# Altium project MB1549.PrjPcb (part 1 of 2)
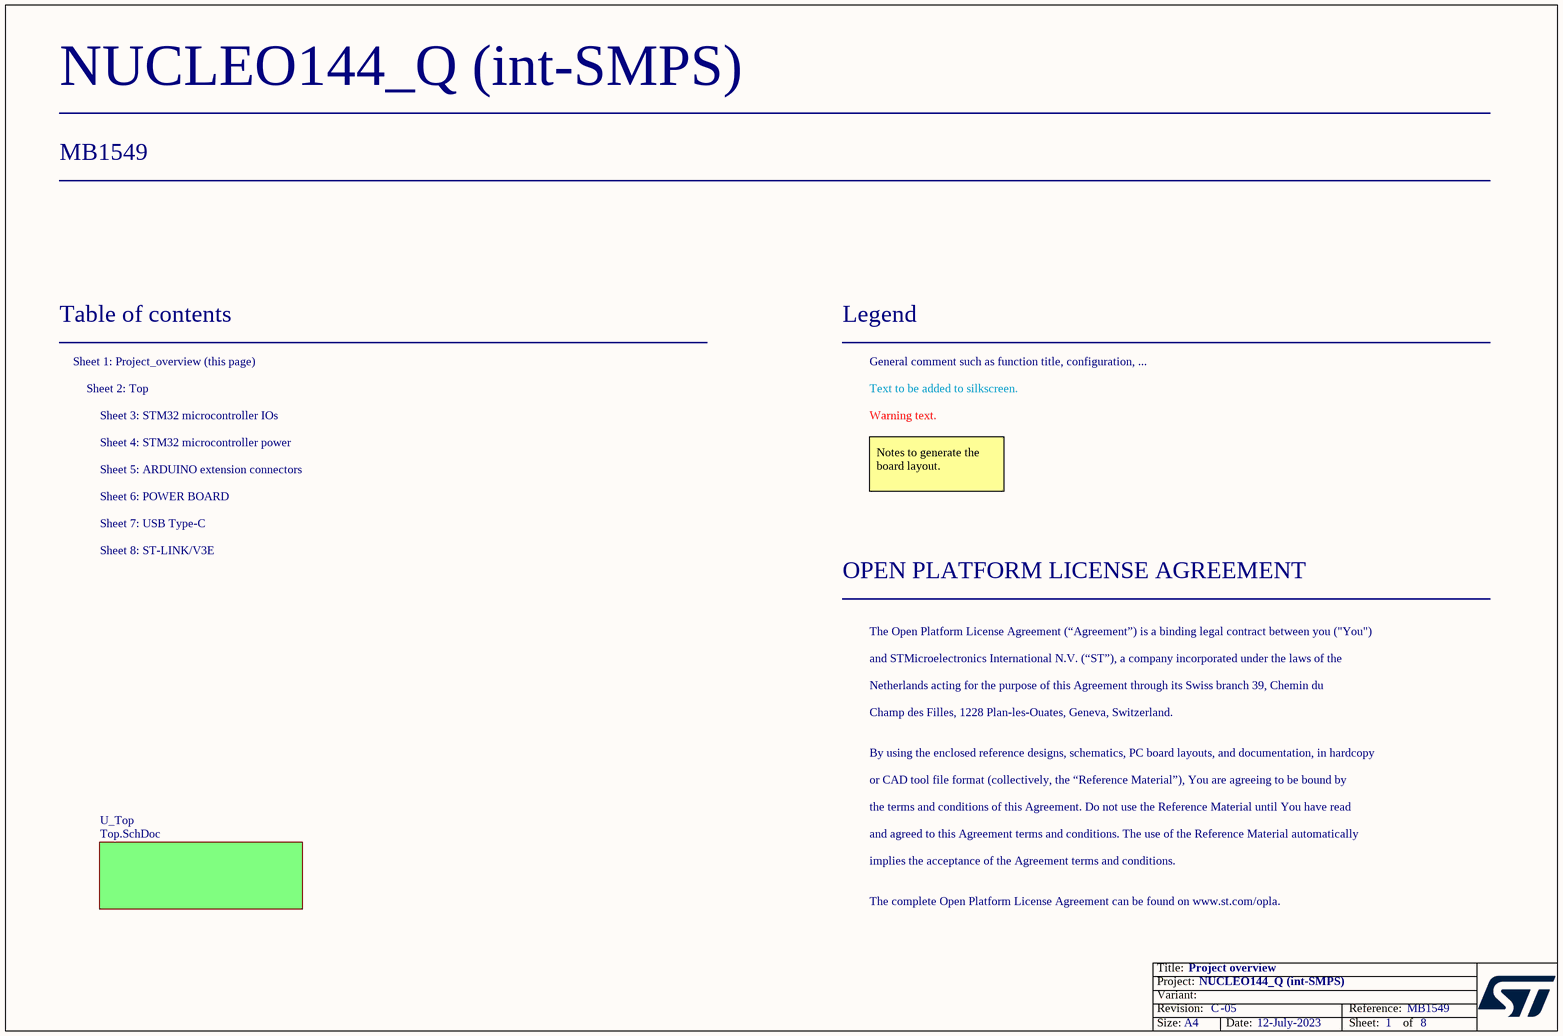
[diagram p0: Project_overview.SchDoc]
Board_Reference: MB1549; Board_PCB_Revision: C; Board_Name: NUCLEO144_Q (int-SMPS); Board_Document_Date: 12-July-2023; Board_Assembly_Revision: 05
8 sheets, 291 parts. Net scope: flat (ports and power ports of the same name join across sheets).
Board file: MB1549.PcbDoc
Sheets:
  Project_overview.SchDoc
    U_Top = Top.SchDoc
      U_STM32_microcontroller_IOs = STM32_microcontroller_IOs.SchDoc
      U_STM32_microcontroller_power = STM32_microcontroller_power.SchDoc
      U_ARDUINO_extension_connectors = ARDUINO_extension_connectors.SchDoc
      U_USB_Type_C = USB_Type_C.SchDoc
      U_POWER_BOARD = POWER_BOARD.SchDoc
      U_ST_LINK_V3E = ST_LINK_V3E.SchDoc

## Sheet Project_overview.SchDoc: Project overview
size A4; Date: Not used; ApprovedBy: Not used; CheckedBy: Not used; Author: Not used; CompanyName: STMicroelectronics; DrawnBy: Not used; Engineer: Not used; Organization: Not used; Address1: Not used; Address2: Not used; Address3: Not used; Address4: Not used; DocumentNumber: 1; Revision: Not used; SheetNumber: 1; SheetTotal: 8

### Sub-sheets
U_Top = Top.SchDoc: no entries

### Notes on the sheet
- Table of contents
- Sheet 1: Project_overview (this page)
- Legend
- General comment such as function title, configuration, ...
- Sheet 2: Top
- Sheet 4: STM32 microcontroller power
- Sheet 3: STM32 microcontroller IOs
- Text to be added to silkscreen.
- Warning text.
- Sheet 6: POWER BOARD
- Sheet 5: ARDUINO extension connectors
- Notes to generate the board layout.
- Sheet 8: ST-LINK/V3E
- Sheet 7: USB Type-C
- OPEN PLATFORM LICENSE AGREEMENT
- The Open Platform License Agreement (“Agreement”) is a binding legal contract between you ("You")
- and STMicroelectronics International N.V. (“ST”), a company incorporated under the laws of the
- Netherlands acting for the purpose of this Agreement through its Swiss branch 39, Chemin du
- Champ des Filles, 1228 Plan-les-Ouates, Geneva, Switzerland.
- By using the enclosed reference designs, schematics, PC board layouts, and documentation, in hardcopy
- or CAD tool file format (collectively, the “Reference Material”), You are agreeing to be bound by
- the terms and conditions of this Agreement. Do not use the Reference Material until You have read
- and agreed to this Agreement terms and conditions. The use of the Reference Material automatically
- implies the acceptance of the Agreement terms and conditions.
- The complete Open Platform License Agreement can be found on www.st.com/opla.

## Sheet Top.SchDoc: Top: hierarchical view
size A4; Date: Not used; ApprovedBy: Not used; CheckedBy: Not used; Author: Not used; CompanyName: STMicroelectronics; DrawnBy: Not used; Engineer: Not used; Organization: Not used; Address1: Not used; Address2: Not used; Address3: Not used; Address4: Not used; DocumentNumber: 2; Revision: A-01-P3; SheetNumber: 2; SheetTotal: 8
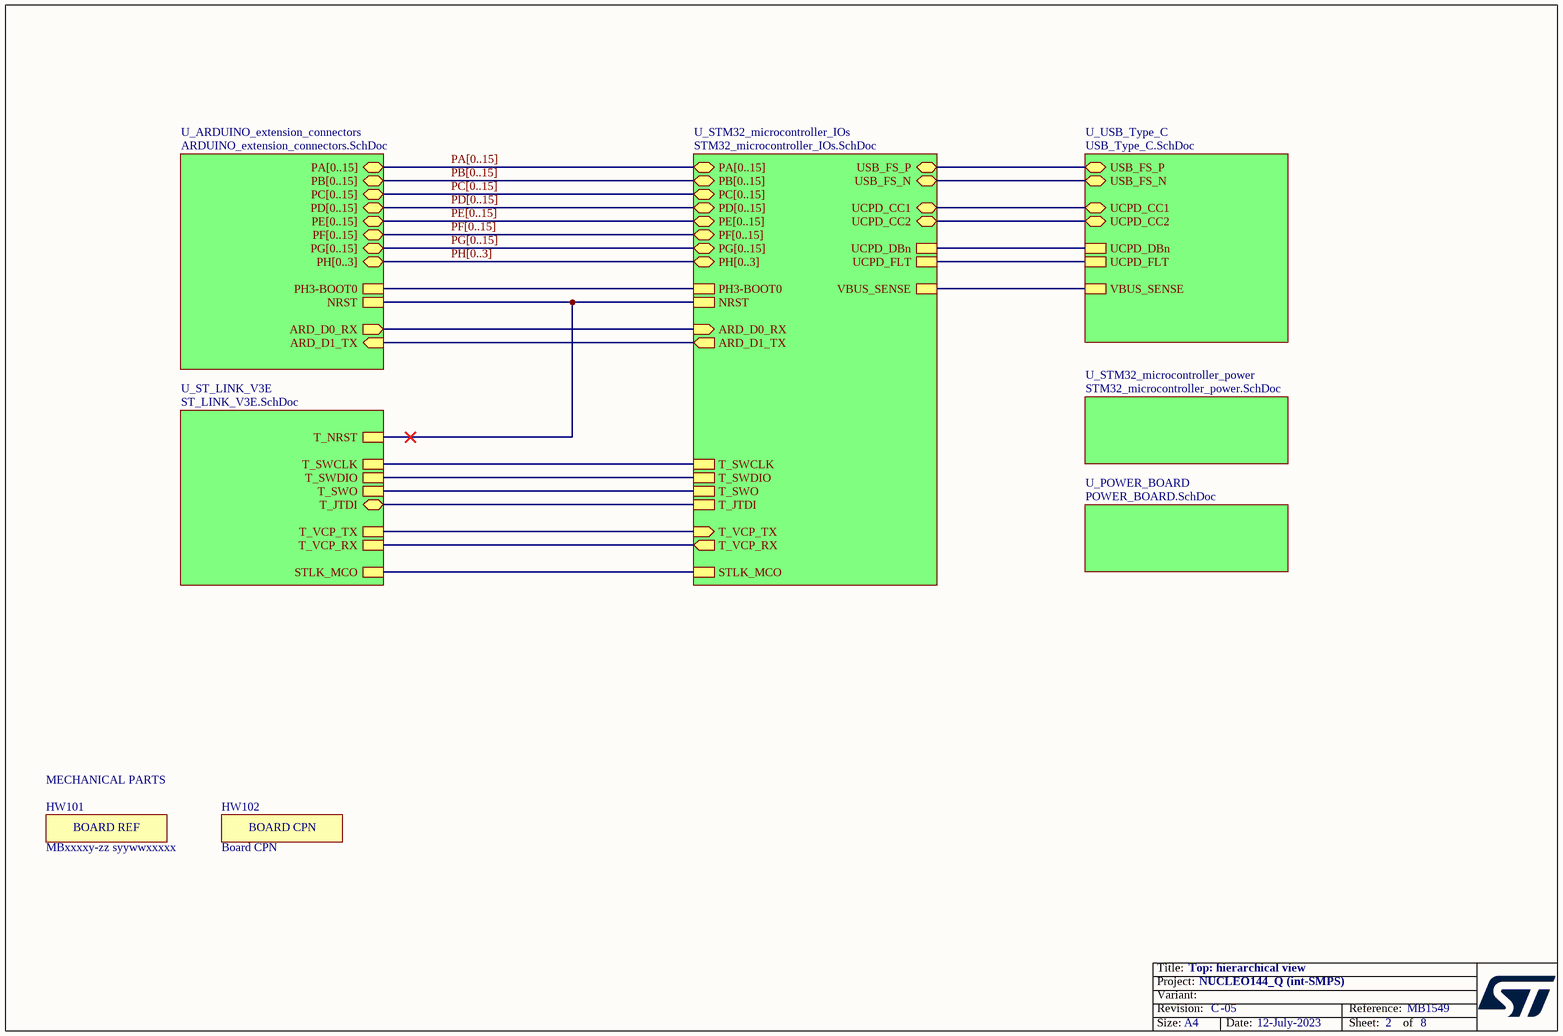
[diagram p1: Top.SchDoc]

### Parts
HW101  value MBxxxxy-zz syywwxxxxx  [STICKER_25X9]  (hidden comment: STICKER_BOARD_REF)  (no BOM)
HW102  value Board CPN  [STICKER_25X9]  (hidden comment: STICKER_BOARD_CPN)  (no BOM)

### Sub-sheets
U_ARDUINO_extension_connectors = ARDUINO_extension_connectors.SchDoc: PA[0..15] (bidir), PB[0..15] (bidir), PC[0..15] (bidir), NRST, PH3-BOOT0, PD[0..15] (bidir), PE[0..15] (bidir), PF[0..15] (bidir), PG[0..15] (bidir), PH[0..3] (bidir), ARD_D0_RX (out), ARD_D1_TX (in)
U_POWER_BOARD = POWER_BOARD.SchDoc: no entries
U_ST_LINK_V3E = ST_LINK_V3E.SchDoc: T_SWDIO, STLK_MCO, T_JTDI (bidir), T_SWO, T_VCP_TX, T_SWCLK, T_VCP_RX, T_NRST
U_STM32_microcontroller_IOs = STM32_microcontroller_IOs.SchDoc: NRST, PA[0..15] (bidir), PB[0..15] (bidir), PC[0..15] (bidir), PD[0..15] (bidir), PE[0..15] (bidir), PF[0..15] (bidir), PG[0..15] (bidir), PH[0..3] (bidir), PH3-BOOT0, ARD_D0_RX (in), ARD_D1_TX (out), UCPD_DBn, UCPD_FLT, VBUS_SENSE, UCPD_CC2 (bidir), USB_FS_P (bidir), UCPD_CC1 (bidir), USB_FS_N (bidir), T_VCP_TX (in), T_VCP_RX (out), T_SWCLK, T_SWDIO, STLK_MCO, T_SWO, T_JTDI
U_STM32_microcontroller_power = STM32_microcontroller_power.SchDoc: no entries
U_USB_Type_C = USB_Type_C.SchDoc: UCPD_CC1 (bidir), UCPD_CC2 (bidir), UCPD_DBn, UCPD_FLT, USB_FS_P (bidir), VBUS_SENSE, USB_FS_N (bidir)

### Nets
(unnamed): sheet U_STM32_microcontroller_IOs/NRST, sheet U_ARDUINO_extension_connectors/NRST, sheet U_ST_LINK_V3E/T_NRST
(unnamed): sheet U_STM32_microcontroller_IOs/PH3-BOOT0, sheet U_ARDUINO_extension_connectors/PH3-BOOT0  [a separate net that carries the same name]
(unnamed): sheet U_STM32_microcontroller_IOs/ARD_D0_RX, sheet U_ARDUINO_extension_connectors/ARD_D0_RX  [a separate net that carries the same name]
(unnamed): sheet U_STM32_microcontroller_IOs/ARD_D1_TX, sheet U_ARDUINO_extension_connectors/ARD_D1_TX  [a separate net that carries the same name]
(unnamed): sheet U_STM32_microcontroller_IOs/UCPD_DBn, sheet U_USB_Type_C/UCPD_DBn  [a separate net that carries the same name]
(unnamed): sheet U_STM32_microcontroller_IOs/UCPD_FLT, sheet U_USB_Type_C/UCPD_FLT  [a separate net that carries the same name]
(unnamed): sheet U_STM32_microcontroller_IOs/VBUS_SENSE, sheet U_USB_Type_C/VBUS_SENSE  [a separate net that carries the same name]
(unnamed): sheet U_STM32_microcontroller_IOs/UCPD_CC2, sheet U_USB_Type_C/UCPD_CC2  [a separate net that carries the same name]
(unnamed): sheet U_STM32_microcontroller_IOs/USB_FS_P, sheet U_USB_Type_C/USB_FS_P  [a separate net that carries the same name]
(unnamed): sheet U_STM32_microcontroller_IOs/UCPD_CC1, sheet U_USB_Type_C/UCPD_CC1  [a separate net that carries the same name]
(unnamed): sheet U_STM32_microcontroller_IOs/USB_FS_N, sheet U_USB_Type_C/USB_FS_N  [a separate net that carries the same name]
(unnamed): sheet U_STM32_microcontroller_IOs/T_VCP_TX, sheet U_ST_LINK_V3E/T_VCP_TX  [a separate net that carries the same name]
(unnamed): sheet U_STM32_microcontroller_IOs/T_VCP_RX, sheet U_ST_LINK_V3E/T_VCP_RX  [a separate net that carries the same name]
(unnamed): sheet U_STM32_microcontroller_IOs/T_SWCLK, sheet U_ST_LINK_V3E/T_SWCLK  [a separate net that carries the same name]
(unnamed): sheet U_STM32_microcontroller_IOs/T_SWDIO, sheet U_ST_LINK_V3E/T_SWDIO  [a separate net that carries the same name]
(unnamed): sheet U_STM32_microcontroller_IOs/STLK_MCO, sheet U_ST_LINK_V3E/STLK_MCO  [a separate net that carries the same name]
(unnamed): sheet U_STM32_microcontroller_IOs/T_SWO, sheet U_ST_LINK_V3E/T_SWO  [a separate net that carries the same name]
(unnamed): sheet U_STM32_microcontroller_IOs/T_JTDI, sheet U_ST_LINK_V3E/T_JTDI  [a separate net that carries the same name]

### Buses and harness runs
bus PA[0..15] = sheet U_ARDUINO_extension_connectors/PA[0..15] = sheet U_STM32_microcontroller_IOs/PA[0..15]
bus PB[0..15] = sheet U_ARDUINO_extension_connectors/PB[0..15] = sheet U_STM32_microcontroller_IOs/PB[0..15]
bus PC[0..15] = sheet U_ARDUINO_extension_connectors/PC[0..15] = sheet U_STM32_microcontroller_IOs/PC[0..15]
bus PD[0..15] = sheet U_ARDUINO_extension_connectors/PD[0..15] = sheet U_STM32_microcontroller_IOs/PD[0..15]
bus PE[0..15] = sheet U_ARDUINO_extension_connectors/PE[0..15] = sheet U_STM32_microcontroller_IOs/PE[0..15]
bus PF[0..15] = sheet U_ARDUINO_extension_connectors/PF[0..15] = sheet U_STM32_microcontroller_IOs/PF[0..15]
bus PG[0..15] = sheet U_ARDUINO_extension_connectors/PG[0..15] = sheet U_STM32_microcontroller_IOs/PG[0..15]
bus PH[0..3] = sheet U_ARDUINO_extension_connectors/PH[0..3] = sheet U_STM32_microcontroller_IOs/PH[0..3]

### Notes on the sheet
- (near HW101) MECHANICAL PARTS

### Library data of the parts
HW101 = MCD-00235: Sticker to mention board reference + serial number; Part_Type: Mechanical; Provided_By: SUBCO
HW102 = MCD-00547: Sticker to mention board CPN code; Part_Type: Mechanical; Provided_By: SUBCO

## Sheet STM32_microcontroller_IOs.SchDoc: STM32_microcontroller_IOs
size A4; Date: Not used; ApprovedBy: Not used; CheckedBy: Not used; Author: Not used; CompanyName: STMicroelectronics; DrawnBy: Not used; Engineer: Not used; Organization: Not used; Address1: Not used; Address2: Not used; Address3: Not used; Address4: Not used; DocumentNumber: 3; Revision: Not used; SheetNumber: 3; SheetTotal: 8
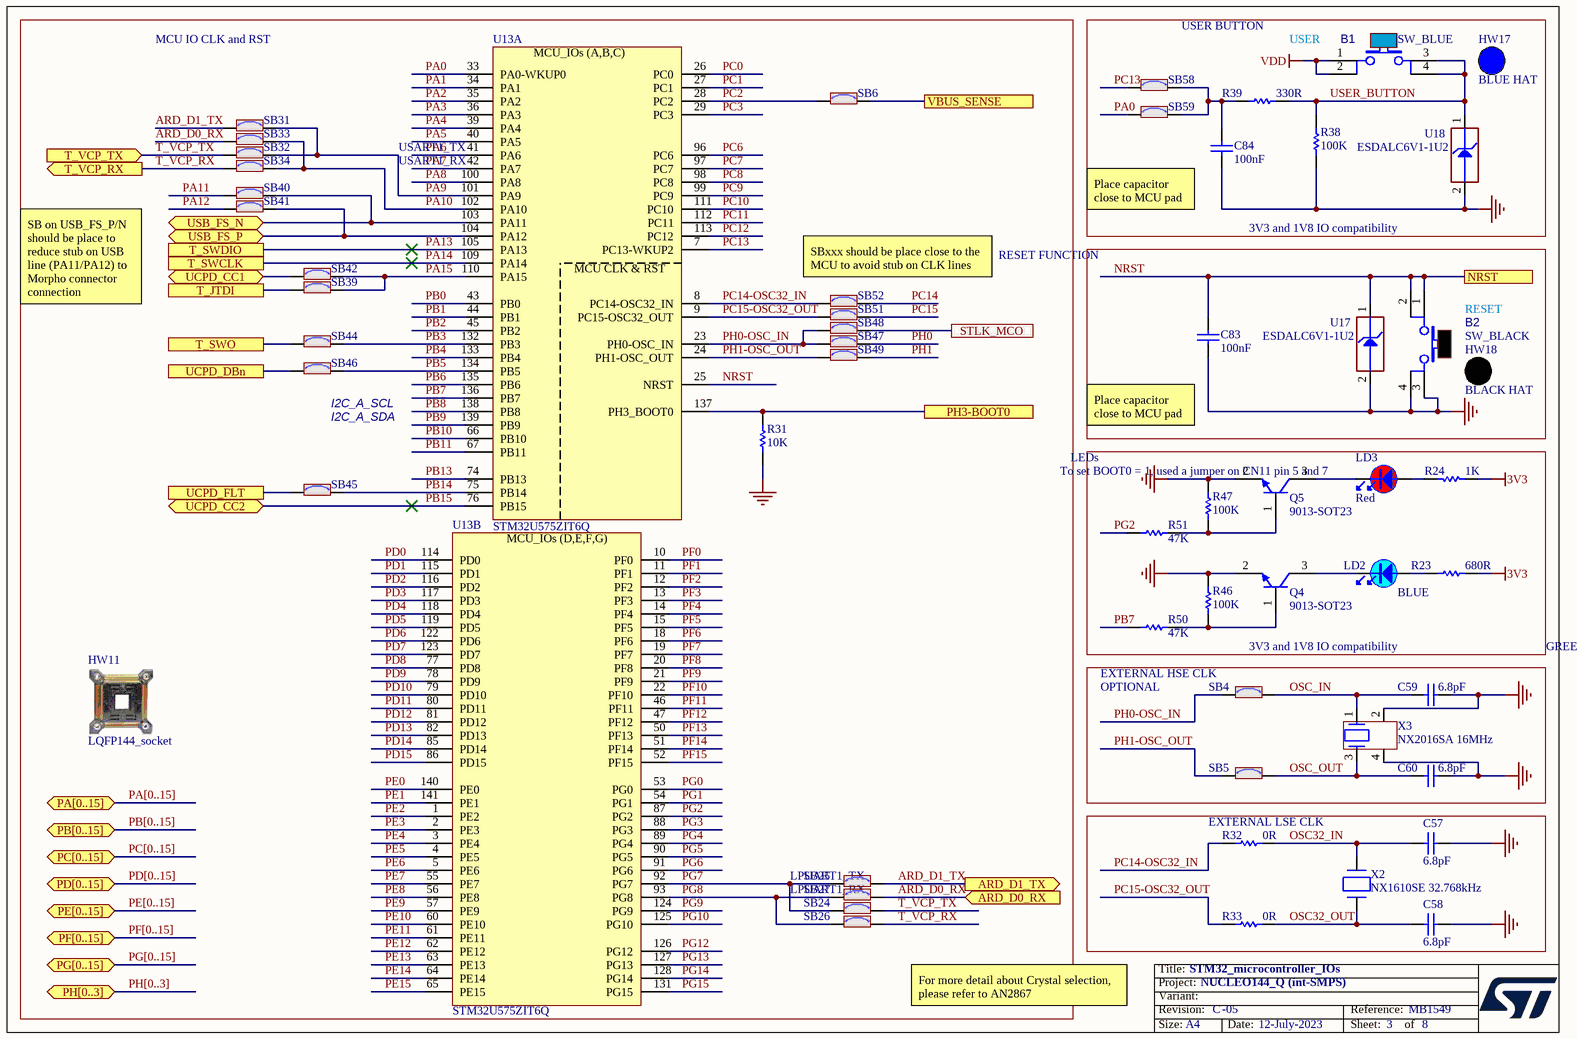
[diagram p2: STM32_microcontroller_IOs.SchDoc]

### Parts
B1  value SW_BLUE  [SWI_WEALTHMETAL_TD-0341_4P_BLUE]
B2  value SW_BLACK  [SWI_WEALTHMETAL_TD-0341_4P_BLACK]
C57  value 6.8pF  [C0402]  (hidden comment: Capacitor)
C58  value 6.8pF  [C0402]  (hidden comment: Capacitor)
C59  value 6.8pF  [C0402]  (hidden comment: Capacitor)
C60  value 6.8pF  [C0402]  (hidden comment: Capacitor)
C83  value 100nF  [C0402]
C84  value 100nF  [C0402]
HW11  value LQFP144_socket  (mechanical)
HW17  value BLUE HAT  (mechanical)
HW18  value BLACK HAT  (mechanical)
LD2  value BLUE  [LED_0603_VISHAY_VLMB1300-GS08_BLUE_1A2K_H0P8]
LD3  value Red  [LED_0603_RED]  (hidden comment: LED_red)
Q4  value 9013-SOT23  [NPN_SOT23]
Q5  value 9013-SOT23  [NPN_SOT23]
R23  value 680R  [R0603]
R24  value 1K  [R0603]
R31  value 10K  [R0402]  (hidden comment: Resistor)
R32  value 0R  [R0603]
R33  value 0R  [R0603]
R38  value 100K  [R0603]
R39  value 330R  [R0603]
R46  value 100K  [R0603]
R47  value 100K  [R0603]
R50  value 47K  [R0603]
R51  value 47K  [R0603]
SB4  (no value)  [SOLDER-BRIDGE_R0603-0R]
SB5  (no value)  [SOLDER-BRIDGE_R0603-0R]
SB6  (no value)  [SOLDER-BRIDGE_R0603-0R]
SB24  (no value)  [SOLDER-BRIDGE_R0603-0R]
SB25  (no value)  [SOLDER-BRIDGE_R0603-0R]
SB26  (no value)  [SOLDER-BRIDGE_R0603-0R]
SB27  (no value)  [SOLDER-BRIDGE_R0603-0R]
SB31  (no value)  [SOLDER-BRIDGE_R0603-0R]
SB32  (no value)  [SOLDER-BRIDGE_R0603-0R]
SB33  (no value)  [SOLDER-BRIDGE_R0603-0R]
SB34  (no value)  [SOLDER-BRIDGE_R0603-0R]
SB39  (no value)  [SOLDER-BRIDGE_R0603-0R]
SB40  (no value)  [SOLDER-BRIDGE_R0603-0R]
SB41  (no value)  [SOLDER-BRIDGE_R0603-0R]
SB42  (no value)  [SOLDER-BRIDGE_R0603-0R]
SB44  (no value)  [SOLDER-BRIDGE_R0603-0R]
SB45  (no value)  [SOLDER-BRIDGE_R0603-0R]
SB46  (no value)  [SOLDER-BRIDGE_R0603-0R]
SB47  (no value)  [SOLDER-BRIDGE_R0603-0R]
SB48  (no value)  [SOLDER-BRIDGE_R0603-0R]
SB49  (no value)  [SOLDER-BRIDGE_R0603-0R]
SB51  (no value)  [SOLDER-BRIDGE_R0603-0R]
SB52  (no value)  [SOLDER-BRIDGE_R0603-0R]
SB58  (no value)  [SOLDER-BRIDGE_R0603-0R]
SB59  (no value)  [SOLDER-BRIDGE_R0603-0R]
U13  value STM32U575ZIT6Q  [ICC_LQFP144_20X20_P050]  (hidden comment: STM32U575ZIT6QU)  (parts A,B of 3)
U17  value ESDALC6V1-1U2  [ESD_ST0201]
U18  value ESDALC6V1-1U2  [ESD_ST0201]
X2  value NX1610SE 32.768kHz  [CRY_NX1610SE_2P]  (hidden comment: XTAL_2_PINS)
X3  value NX2016SA 16MHz  [CRY_NX2016SA_4P]  (hidden comment: XTAL_4_PINS)

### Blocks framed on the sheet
EXTERNAL LSE CLK: C57 C58 R32 R33 X2

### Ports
ARD_D0_RX (in), ARD_D1_TX (out), NRST, PA[0..15] (bidir), PB[0..15] (bidir), PC[0..15] (bidir), PD[0..15] (bidir), PE[0..15] (bidir), PF[0..15] (bidir), PG[0..15] (bidir), PH3-BOOT0, PH[0..3] (bidir), STLK_MCO, T_JTDI, T_SWCLK, T_SWDIO, T_SWO, T_VCP_RX (out), T_VCP_TX (in), UCPD_CC1 (bidir), UCPD_CC2 (bidir), UCPD_DBn, UCPD_FLT, USB_FS_N (bidir), USB_FS_P (bidir), VBUS_SENSE

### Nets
3V3: R23.1 R24.1
GND: B2.3 B2.4 C57.2 C58.2 C59.2 C60.2 C83.1 C84.1 Q4.2(E) Q5.2(E) R31.2 R38.1 R46.1 R47.1 U17.2(GND) U18.2(GND) X3.2 X3.4
VDD: B1.1 B1.2
ARD_D0_RX: SB27.1 SB33.2 ; port ARD_D0_RX
ARD_D1_TX: SB25.1 SB31.2 ; port ARD_D1_TX
NRST: B2.1 B2.2 C83.2 U13.25(NRST) U17.1(IO1) ; port NRST
OSC32_IN: C57.1 R32.2 X2.2(X2)
OSC32_OUT: C58.1 R33.2 X2.1(X1)
OSC_IN: C59.1 SB4.2 X3.1
OSC_OUT: C60.1 SB5.2 X3.3
PA0: SB59.2 U13.33(PA0-WKUP0)
PA1: U13.34(PA1)
PA2: U13.35(PA2)
PA3: U13.36(PA3)
PA4: U13.39(PA4)
PA5: U13.40(PA5)
PA6: U13.41(PA6)
PA7: U13.42(PA7)
PA8: U13.100(PA8)
PA9: SB31.1 SB32.1 U13.101(PA9)
PA10: SB33.1 SB34.1 U13.102(PA10)
PA11: SB40.1
PA12: SB41.1
PA13: U13.105(PA13) ; port T_SWDIO
PA14: U13.109(PA14) ; port T_SWCLK
PA15: SB39.2 SB42.2 U13.110(PA15)
PB0: U13.43(PB0)
PB1: U13.44(PB1)
PB2: U13.45(PB2)
PB3: SB44.2 U13.132(PB3)
PB4: U13.133(PB4)
PB5: SB46.2 U13.134(PB5)
PB6: U13.135(PB6)
PB7: R50.1 U13.136(PB7)
PB8: U13.138(PB8)
PB9: U13.139(PB9)
PB10: U13.66(PB10)
PB11: U13.67(PB11)
PB13: U13.74(PB13)
PB14: SB45.2 U13.75(PB14)
PB15: U13.76(PB15) ; port UCPD_CC2
PC0: U13.26(PC0)
PC1: U13.27(PC1)
PC2: SB6.1 U13.28(PC2)
PC3: U13.29(PC3)
PC6: U13.96(PC6)
PC7: U13.97(PC7)
PC8: U13.98(PC8)
PC9: U13.99(PC9)
PC10: U13.111(PC10)
PC11: U13.112(PC11)
PC12: U13.113(PC12)
PC13: SB58.2 U13.7(PC13-WKUP2)
PC14: SB52.2
PC14-OSC32_IN: R32.1 SB52.1 U13.8(PC14-OSC32_IN)
PC15: SB51.2
PC15-OSC32_OUT: R33.1 SB51.1 U13.9(PC15-OSC32_OUT)
PD0: U13.114(PD0)
PD1: U13.115(PD1)
PD2: U13.116(PD2)
PD3: U13.117(PD3)
PD4: U13.118(PD4)
PD5: U13.119(PD5)
PD6: U13.122(PD6)
PD7: U13.123(PD7)
PD8: U13.77(PD8)
PD9: U13.78(PD9)
PD10: U13.79(PD10)
PD11: U13.80(PD11)
PD12: U13.81(PD12)
PD13: U13.82(PD13)
PD14: U13.85(PD14)
PD15: U13.86(PD15)
PE0: U13.140(PE0)
PE1: U13.141(PE1)
PE2: U13.1(PE2)
PE3: U13.2(PE3)
PE4: U13.3(PE4)
PE5: U13.4(PE5)
PE6: U13.5(PE6)
PE7: U13.55(PE7)
PE8: U13.56(PE8)
PE9: U13.57(PE9)
PE10: U13.60(PE10)
PE11: U13.61(PE11)
PE12: U13.62(PE12)
PE13: U13.63(PE13)
PE14: U13.64(PE14)
PE15: U13.65(PE15)
PF0: U13.10(PF0)
PF1: U13.11(PF1)
PF2: U13.12(PF2)
PF3: U13.13(PF3)
PF4: U13.14(PF4)
PF5: U13.15(PF5)
PF6: U13.18(PF6)
PF7: U13.19(PF7)
PF8: U13.20(PF8)
PF9: U13.21(PF9)
PF10: U13.22(PF10)
PF11: U13.46(PF11)
PF12: U13.47(PF12)
PF13: U13.50(PF13)
PF14: U13.51(PF14)
PF15: U13.52(PF15)
PG0: U13.53(PG0)
PG1: U13.54(PG1)
PG2: R51.1 U13.87(PG2)
PG3: U13.88(PG3)
PG4: U13.89(PG4)
PG5: U13.90(PG5)
PG6: U13.91(PG6)
PG7: SB24.2 SB25.2 U13.92(PG7)
PG8: SB26.2 SB27.2 U13.93(PG8)
PG9: U13.124(PG9)
PG10: U13.125(PG10)
PG12: U13.126(PG12)
PG13: U13.127(PG13)
PG14: U13.128(PG14)
PG15: U13.131(PG15)
PH0: SB47.2
PH0-OSC_IN: SB4.1 SB47.1 SB48.1 U13.23(PH0-OSC_IN)
PH1: SB49.2
PH1-OSC_OUT: SB5.1 SB49.1 U13.24(PH1-OSC_OUT)
PH3-BOOT0: R31.1 U13.137(PH3_BOOT0) ; port PH3-BOOT0
STLK_MCO: SB48.2 ; port STLK_MCO
T_JTDI: SB39.1 ; port T_JTDI
T_SWO: SB44.1 ; port T_SWO
T_VCP_RX: SB26.1 SB34.2 ; port T_VCP_RX
T_VCP_TX: SB24.1 SB32.2 ; port T_VCP_TX
UCPD_CC1: SB42.1 ; port UCPD_CC1
UCPD_DBn: SB46.1 ; port UCPD_DBn
UCPD_FLT: SB45.1 ; port UCPD_FLT
USB_FS_N: SB40.2 U13.103(PA11) ; port USB_FS_N
USB_FS_P: SB41.2 U13.104(PA12) ; port USB_FS_P
USER_BUTTON: B1.3 B1.4 R38.2 R39.2 U18.1(IO1)
VBUS_SENSE: SB6.2 ; port VBUS_SENSE
NetC84_2: C84.2 R39.1 SB58.1 SB59.1
NetLD2_1: LD2.1 R23.2
NetLD2_2: LD2.2 Q4.3(C)
NetLD3_1: LD3.1 R24.2
NetLD3_2: LD3.2 Q5.3(C)
NetQ4_1: Q4.1(B) R46.2 R50.2
NetQ5_1: Q5.1(B) R47.2 R51.2

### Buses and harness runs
bus PA[0..15] = port PA[0..15]
bus PB[0..15] = port PB[0..15]
bus PC[0..15] = port PC[0..15]
bus PD[0..15] = port PD[0..15]
bus PE[0..15] = port PE[0..15]
bus PF[0..15] = port PF[0..15]
bus PG[0..15] = port PG[0..15]
bus PH[0..3] = port PH[0..3]

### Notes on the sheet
- MCU IO CLK and RST
- USER BUTTON
- USER
- USART1_TX
- USART1_RX
- (near C84) Place capacitor close to MCU pad
- 3V3 and 1V8 IO compatibility
- SB on USB_FS_P/N should be place to reduce stub on USB line (PA11/PA12) to Morpho connector connection
- SBxxx should be place close to the MCU to avoid stub on CLK lines
- RESET FUNCTION
- RESET
- (near SB46) I2C_A_SCL
- (near SB46) I2C_A_SDA
- (near C83) Place capacitor close to MCU pad
- (near R31) To set BOOT0 = 1, used a jumper on CN11 pin 5 and 7
- LEDs
- (near R50) 3V3 and 1V8 IO compatibility
- (near C59) GREEN LED IS ON ARDUINO SHEET
- EXTERNAL HSE CLK
- OPTIONAL
- LPUART1_TX
- LPUART1_RX
- For more detail about Crystal selection, please refer to AN2867

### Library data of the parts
B1 = MCD-00002: Non-Open Push-Button 0.1A 24V BLUE; Manufacturer_Part_Number: TD0341X-G01-BLU; Manufacturer: WEALTHMETAL; Part_Type: Misc; Provided_By: Subcon; Initial_Board_Reference: MB1274
B2 = MCD-00001: Non-Open Push-Button 0.1A 24V BLACK; Manufacturer_Part_Number: TD0341X-G01-BLA; Manufacturer: WEALTHMETAL; Part_Type: Misc; Provided_By: Subcon; Initial_Board_Reference: MB1274
C57 C58 = MCD-00674: Capacitor, MLCC, 6.8pF, 50V, NPO, +/-0.25pF, 0402, T=0.5mm; Part_Preference: Recommended; Manufacturer: YAGEO; Manufacturer_Part_Number: CC0402CRNPO9BN6R8; Component_Country_Of_Origin: China; ShowFields: YES; ID: 3068
C59 C60 = MCD-00674: Capacitor, MLCC, 6.8pF, 50V, NPO, +-0.25pF, 0402, T=0.5mm; Manufacturer_Part_Number: CC0402CRNPO9BN6R8; Manufacturer: YAGEO; Provided_By: Subcon; Initial_Board_Reference: MB1319
C83 C84 = MCD-00006: Capacitor, MLCC, 100nF, 16V, X7R, 10%, 0402, T=0.5mm; Manufacturer_Part_Number: CC0402KRX7R7BB104; Manufacturer: YAGEO; Alternate_Manufacturer_Part_Number: GCM155R71C104KA55D; Alternate_Manufacturer: MURATA; Provided_By: SUBCO; ECCN_US: EAR99; ECCN_EU: NEC
HW11 = MCD-01015: Yamaichi socket for LQFP144, with positioning pins.; Part_Type: Misc; Manufacturer_Part_Number: IC149-144-145-B5; Provided_By: Subcon; Initial_Board_Reference: MB1361; Remark: No footprint, mechanical part for BOM
HW17 = MCD-00634: Blue Hat for switch TD0341X-G01-BLU; Part_Type: Mechanical; Manufacturer_Part_Number: 988.16.09.3.00002_SH-517; Manufacturer: JIUBABA; Provided_By: Subcon; Initial_Board_Reference: MB1319
HW18 = MCD-00635: Black Hat for switch TD0341X-G01-BLA; Part_Type: Mechanical; Manufacturer_Part_Number: 988.16.09.3.00003_SH-517; Manufacturer: JIUBABA; Provided_By: Subcon; Initial_Board_Reference: MB1319
LD2 = MCD-00584: LED Blue, 0603 SMD, 3.3 V Forward Voltage; Part_Type: Display; Manufacturer_Part_Number: VLMB1300-GS08; Manufacturer: VISHAY; Order_Code_RS: 7730430; Provided_By: Subcon; Initial_Board_Reference: MB1331
LD3 = MCD-02899: LED, Red, 2V35, 20mA, 0603; Part_Type: Display; Part_Preference: Recommended; Manufacturer: EVERLIGHT; Manufacturer_Part_Number: 19-213/R6C-AP1Q2B/5T; Full_Alternate_Internal_Part_Number: MCD-00049; Component_Country_Of_Origin: China; ShowFields: YES; ID: 5015
Q4 Q5 = MCD-00073: NPN Bipolar Transistor; Part_Type: IC; Manufacturer_Part_Number: BSR14; Manufacturer: NXP; ECCN_US: EAR99; ECCN_EU: NEC; Provided_By: Subcon; Initial_Board_Reference: MB1274
R23 = MCD-00508: Resistor,680R,0603,1%,1/10W; Manufacturer_Part_Number: RC0603FR-07680RL; Manufacturer: YAGEO; Provided_By: Subcon
R24 = MCD-00070: Resistor,1K,0603,1%,1/10W; Manufacturer_Part_Number: RC0603FR-071KL; Manufacturer: YAGEO; Provided_By: Subcon; Initial_Board_Reference: MB1274
R31 = MCD-00053: Resistor,10K,0402,1%,1/16W; Manufacturer_Part_Number: RC0402FR-0710KL; Manufacturer: YAGEO; ECCN_US: EAR99; ECCN_EU: NEC; Provided_By: SUBCO
R32 R33 = MCD-00056: Resistor,0R,0603,5%,1/10W; Manufacturer_Part_Number: RC0603JR-070RL; Manufacturer: YAGEO; Provided_By: subcon; Initial_Board_Reference: MB1274
R38 R46 R47 = MCD-00223: Resistor,100K,0603,1%,1/10W; Manufacturer_Part_Number: RC0603FR-07100KL; Manufacturer: YAGEO; Provided_By: Subcon; Initial_Board_Reference: MB1319
R39 = MCD-00197: Resistor,330R,0603,1%,1/10W; Manufacturer_Part_Number: RC0603FR-07330RL; Manufacturer: YAGEO; Provided_By: Subcon
R50 R51 = MCD-00222: Resistor,47K,0603,1%,1/10W; Manufacturer_Part_Number: RC0603FR-0747KL; Manufacturer: YAGEO; Provided_By: Subcon; Initial_Board_Reference: MB1319
SB4-SB6 SB24-SB27 SB31-SB34 SB39-SB42 SB44-SB49 SB51 SB52 SB58 SB59 = MCD-00071: Solder Bridge ON; Part_Type: Mechanical; Provided_By: Subcon; Initial_Board_Reference: MB1274
U13 = MCD-01884: STM32U575ZIT6Q MCU,Low Power LQFP144 20x20, 0.5, no AES, Q for Int SMPS; Part_Type: IC; Part_Preference: Recommended; Manufacturer: STMICROELECTRONICS; Manufacturer_HQ_COO: EU; Component_Country_Of_Origin: Unknown
U17 U18 = MCD-00170: ESD protection 6V1; Part_Type: Diode; Manufacturer: STMICROELECTRONICS; ECCN_US: EAR99; ECCN_EU: NEC; Provided_By: Subcon; Initial_Board_Reference: MB1274
X2 = MCD-02291: Crystal 32.768kHz, 9pF, -+20ppm, 70Kohm max, SMD; Part_Type: Crystal_Osc; Manufacturer_Part_Number: NX1610SE 32.768KHz EXS00A-MU01499; Manufacturer: NDK; Part_Preference: Recommended
X3 = MCD-01476: Crystal 16 MHz, 8pF, -+20 PPM, R=200Ω, SMD; Part_Type: Crystal_Osc; Manufacturer_Part_Number: NX2016SA 16 MHz EXS00A-CS07826; Manufacturer: NDK; Provided_By: ST; Initial_Board_Reference: MB1373; Item Type: Item; Path: ws/MCD_ApplicationBoards/Lists/MCDPARTSdatabase

## Sheet STM32_microcontroller_power.SchDoc: STM32_microcontroller_power
size A4; Date: Not used; ApprovedBy: Not used; CheckedBy: Not used; Author: Not used; CompanyName: STMicroelectronics; DrawnBy: Not used; Engineer: Not used; Organization: Not used; Address1: Not used; Address2: Not used; Address3: Not used; Address4: Not used; DocumentNumber: 4; Revision: Not used; SheetNumber: 4; SheetTotal: 8
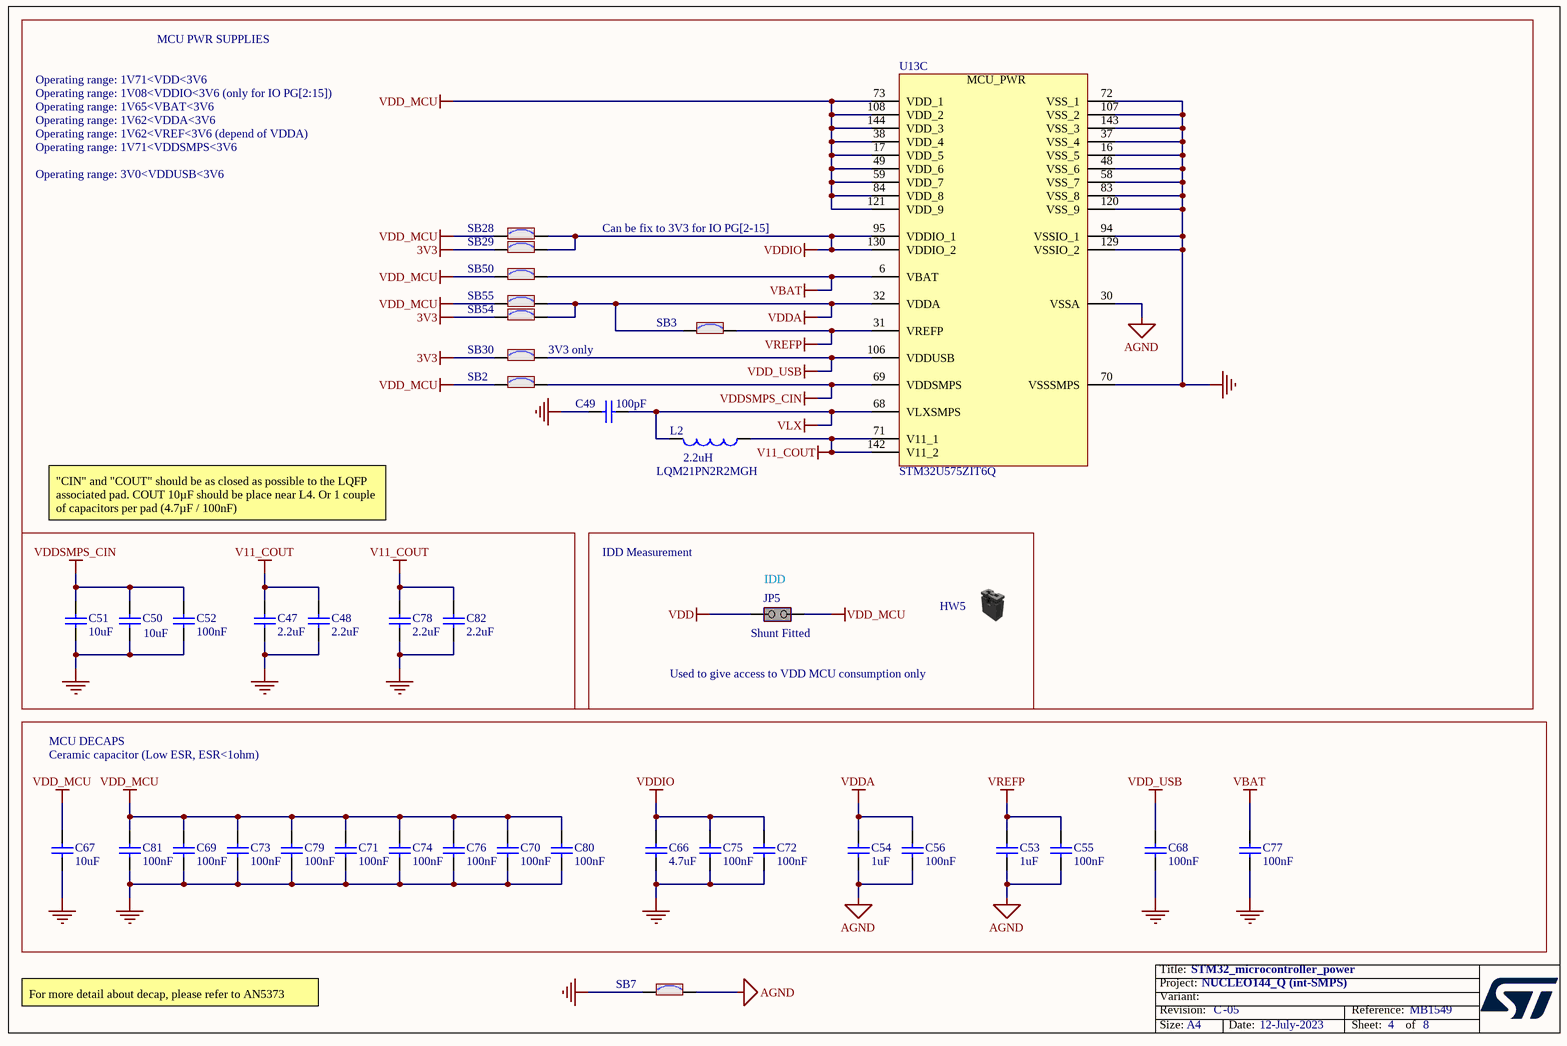
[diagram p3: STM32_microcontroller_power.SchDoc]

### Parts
C47  value 2.2uF  [C0402]  (hidden comment: Capacitor)
C48  value 2.2uF  [C0402]  (hidden comment: Capacitor)
C49  value 100pF  [C0402]
C50  value 10uF  [C0402]
C51  value 10uF  [C0402]
C52  value 100nF  [C0402]
C53  value 1uF  [C0603]  (hidden comment: Capacitor)
C54  value 1uF  [C0603]  (hidden comment: Capacitor)
C55  value 100nF  [C0402]
C56  value 100nF  [C0402]
C66  value 4.7uF  [C0603]  (hidden comment: Capacitor)
C67  value 10uF  [C0402]
C68  value 100nF  [C0402]
C69  value 100nF  [C0402]
C70  value 100nF  [C0402]
C71  value 100nF  [C0402]
C72  value 100nF  [C0402]
C73  value 100nF  [C0402]
C74  value 100nF  [C0402]
C75  value 100nF  [C0402]
C76  value 100nF  [C0402]
C77  value 100nF  [C0402]
C78  value 2.2uF  [C0402]  (hidden comment: Capacitor)
C79  value 100nF  [C0402]
C80  value 100nF  [C0402]
C81  value 100nF  [C0402]
C82  value 2.2uF  [C0402]  (hidden comment: Capacitor)
HW5  (no value)  (mechanical)
JP5  value Shunt Fitted  [CON_SAMTEC_TSW-102-07-G-S]
L2  value 2.2uH  Manufacturer_Part_Number: LQM21PN2R2MGH  [L0805_H0P9]  (hidden comment: Inductor)
SB2  (no value)  [SOLDER-BRIDGE_R0603-0R]
SB3  (no value)  [SOLDER-BRIDGE_R0603-0R]
SB7  (no value)  [SOLDER-BRIDGE_R0603-0R]
SB28  (no value)  [SOLDER-BRIDGE_R0603-0R]
SB29  (no value)  [SOLDER-BRIDGE_R0603-0R]
SB30  (no value)  [SOLDER-BRIDGE_R0603-0R]
SB50  (no value)  [SOLDER-BRIDGE_R0603-0R]
SB54  (no value)  [SOLDER-BRIDGE_R0603-0R]
SB55  (no value)  [SOLDER-BRIDGE_R0603-0R]
U13  value STM32U575ZIT6Q  [ICC_LQFP144_20X20_P050]  (hidden comment: STM32U575ZIT6QU)  (part C of 3)

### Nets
3V3: SB29.1 SB30.1 SB54.1
AGND: C53.2 C54.2 C55.1 C56.1 SB7.2 U13.30(VSSA)
GND: C47.1 C48.1 C49.1 C50.1 C51.1 C52.1 C66.1 C67.1 C68.1 C69.1 C70.1 C71.1 C72.1 C73.1 C74.1 C75.1 C76.1 C77.1 C78.1 C79.1 C80.1 C81.1 C82.1 SB7.1 U13.16(VSS_5) U13.37(VSS_4) U13.48(VSS_6) U13.58(VSS_7) U13.70(VSSSMPS) U13.72(VSS_1) U13.83(VSS_8) U13.94(VSSIO_1) U13.107(VSS_2) U13.120(VSS_9) U13.129(VSSIO_2) U13.143(VSS_3)
V11_COUT: C47.2 C48.2 C78.2 C82.2 L2.1 U13.71(V11_1) U13.142(V11_2)
VBAT: C77.2 SB50.2 U13.6(VBAT)
VDD: JP5.1(COMMON)
VDD_MCU: C67.2 C69.2 C70.2 C71.2 C73.2 C74.2 C76.2 C79.2 C80.2 C81.2 JP5.2(NO) SB2.1 SB28.1 SB50.1 SB55.1 U13.17(VDD_5) U13.38(VDD_4) U13.49(VDD_6) U13.59(VDD_7) U13.73(VDD_1) U13.84(VDD_8) U13.108(VDD_2) U13.121(VDD_9) U13.144(VDD_3)
VDD_USB: C68.2 SB30.2 U13.106(VDDUSB)
VDDA: C54.1 C56.2 SB3.1 SB54.2 SB55.2 U13.32(VDDA)
VDDIO: C66.2 C72.2 C75.2 SB28.2 SB29.2 U13.95(VDDIO_1) U13.130(VDDIO_2)
VDDSMPS_CIN: C50.2 C51.2 C52.2 SB2.2 U13.69(VDDSMPS)
VLX: C49.2 L2.2 U13.68(VLXSMPS)
VREFP: C53.1 C55.2 SB3.2 U13.31(VREFP)

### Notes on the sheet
- MCU PWR SUPPLIES
- Operating range: 1V71<VDD<3V6
- Operating range: 1V08<VDDIO<3V6 (only for IO PG[2:15])
- Operating range: 1V65<VBAT<3V6
- Operating range: 1V62<VDDA<3V6
- Operating range: 3V0<VDDUSB<3V6
- Operating range: 1V71<VDDSMPS<3V6
- Operating range: 1V62<VREF<3V6 (depend of VDDA)
- Can be fix to 3V3 for IO PG[2-15]
- (near SB30) 3V3 only
- "CIN" and "COUT" should be as closed as possible to the LQFP associated pad. COUT 10µF should be place near L4. Or 1 couple of capacitors per pad (4.7µF / 100nF)
- IDD Measurement
- (near JP5) IDD
- Used to give access to VDD MCU consumption only
- MCU DECAPS
- Ceramic capacitor (Low ESR, ESR<1ohm)
- For more detail about decap, please refer to AN5373

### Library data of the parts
C47 C48 C78 C82 = MCD-01823: Capacitor,MLCC,2.2uF,6V3,X5R,10%,0402,T=0.5; Manufacturer_Part_Number: GRM155R60J225KE95D; Manufacturer: MURATA; ECCN_US: EAR99; ECCN_EU: NEC; Provided_By: SUBCO
C49 = MCD-00205: Capacitor, MLCC, 100pF, 50V, NPO, 5%, 0402, T=0,5mm; Manufacturer_Part_Number: CC0402JRNPO9BN101; Manufacturer: YAGEO; Provided_By: Subcon; Initial_Board_Reference: MB1361
C50 C51 C67 = MCD-01355: Capacitor, MLCC, 10uF, 4V, X5R, 20%, 0402, T=0,5mm; Manufacturer_Part_Number: GRM155R60G106ME44; Manufacturer: MURATA; ECCN_US: EAR99; ECCN_EU: NEC; Provided_By: Subcon; Initial_Board_Reference: MB1372
C52 C55 C56 C68-C77 C79-C81 = MCD-00006: as C83 on sheet STM32_microcontroller_IOs
C53 C54 = MCD-00010: Capacitor, MLCC, 1uF, 16V, X5R, 10%, 0603, T=0,8mm; Manufacturer_Part_Number: CC0603KRX5R7BB105; Manufacturer: YAGEO; Provided_By: SUBCO
C66 = MCD-00009: Capacitor, MLCC, 4.7uF, 16V, X5R, 10%, 0603, T=0.8mm; Manufacturer_Part_Number: CC0603KRX5R7BB475; Manufacturer: YAGEO; Provided_By: SUBCO; ECCN_US: EAR99; ECCN_EU: NEC
HW5 = MCD-00043: SHUNT 2.54mm BLACK; Manufacturer_Part_Number: SNT-100-BK-G; Manufacturer: SAMTEC; Part_Type: Mechanical; Provided_By: Subcon; Initial_Board_Reference: MB1274
JP5 = MCD-00683: Header, 2x1, 2,54mm, VR, TH, Height 5.84mm/2.54mm - Shunt Fitted by default; Part_Type: Connector; Manufacturer_Part_Number: TSW-102-07-x-S; Manufacturer: SAMTEC; Provided_By: Subcon; Initial_Board_Reference: MB1331
L2 = MCD-01060: Inductor, 2.2uH, 20%, Isat 0.7A, DCR 0.156Ohm, 0805; Manufacturer: MURATA; ECCN_US: EAR99; Provided_By: SUBCO
SB2 SB3 SB7 SB28-SB30 SB50 SB54 SB55 = MCD-00071: as SB4 on sheet STM32_microcontroller_IOs
U13 = MCD-01884: as U13 on sheet STM32_microcontroller_IOs

## Sheet ARDUINO_extension_connectors.SchDoc: ARDUINO_extension_connectors
size A3; Date: Not used; ApprovedBy: Not used; CheckedBy: Not used; Author: Not used; CompanyName: STMicroelectronics; DrawnBy: Not used; Engineer: Not used; Organization: Not used; Address1: Not used; Address2: Not used; Address3: Not used; Address4: Not used; DocumentNumber: 5; Revision: Not used; SheetNumber: 5; SheetTotal: 8
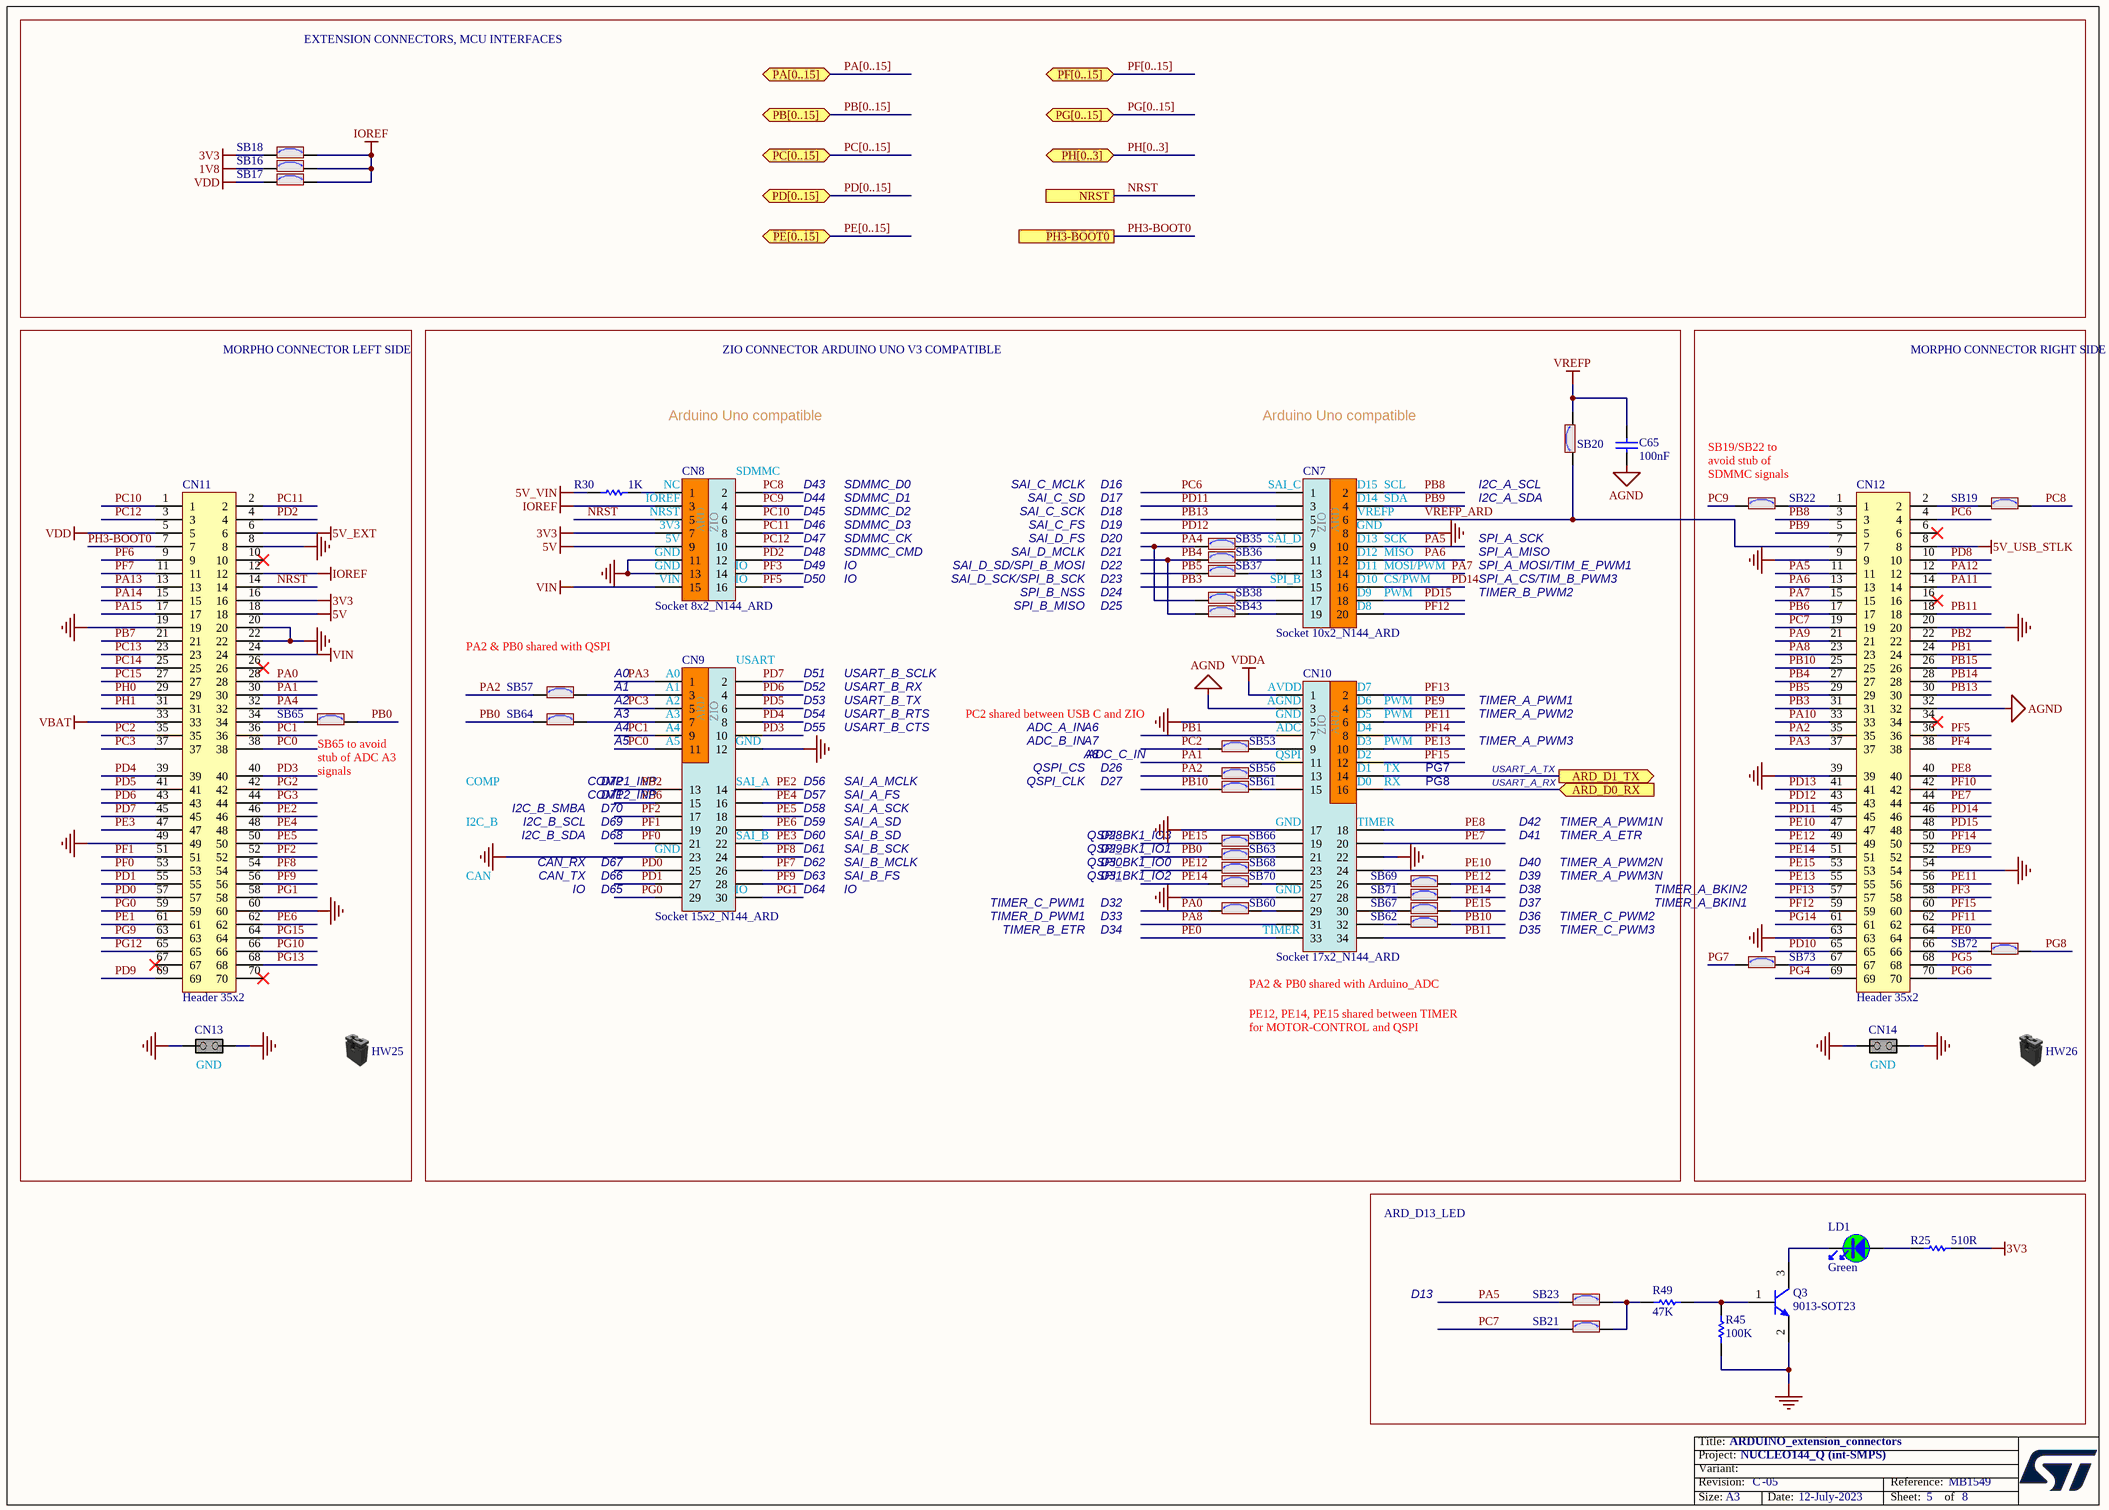
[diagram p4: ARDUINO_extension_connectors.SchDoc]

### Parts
C65  value 100nF  [C0402]
CN7  value Socket 10x2_N144_ARD  [CON_SAMTEC_SSW-110-23-X-D_N144_ARD]
CN8  value Socket 8x2_N144_ARD  [CON_SAMTEC_SSW-108-23-X-D_N144_ARD]
CN9  value Socket 15x2_N144_ARD  [CON_SAMTEC_SSW-115-23-X-D_N144_ARD]
CN10  value Socket 17x2_N144_ARD  [CON_SAMTEC_SSW-117-23-X-D_N144_ARD]
CN11  Header 35x2  [CON_SAMTEC_TSW-135-07-X-D]
CN12  Header 35x2  [CON_SAMTEC_TSW-135-07-X-D]
CN13  (no value)  [CON_SAMTEC_TSW-102-09-X-S]
CN14  (no value)  [CON_SAMTEC_TSW-102-09-X-S]
HW25  (no value)  (mechanical)
HW26  (no value)  (mechanical)
LD1  value Green  [LED_0603_GREEN]  (hidden comment: LED_green)
Q3  value 9013-SOT23  [NPN_SOT23]
R25  value 510R  [R0603]
R30  value 1K  [R0603]
R45  value 100K  [R0603]
R49  value 47K  [R0603]
SB16  (no value)  [SOLDER-BRIDGE_R0603-0R]
SB17  (no value)  [SOLDER-BRIDGE_R0603-0R]
SB18  (no value)  [SOLDER-BRIDGE_R0603-0R]
SB19  (no value)  [SOLDER-BRIDGE_R0603-0R]
SB20  (no value)  [SOLDER-BRIDGE_R0603-0R]
SB21  (no value)  [SOLDER-BRIDGE_R0603-0R]
SB22  (no value)  [SOLDER-BRIDGE_R0603-0R]
SB23  (no value)  [SOLDER-BRIDGE_R0603-0R]
SB35  (no value)  [SOLDER-BRIDGE_R0603-0R]
SB36  (no value)  [SOLDER-BRIDGE_R0603-0R]
SB37  (no value)  [SOLDER-BRIDGE_R0603-0R]
SB38  (no value)  [SOLDER-BRIDGE_R0603-0R]
SB43  (no value)  [SOLDER-BRIDGE_R0603-0R]
SB53  (no value)  [SOLDER-BRIDGE_R0603-0R]
SB56  (no value)  [SOLDER-BRIDGE_R0603-0R]
SB57  (no value)  [SOLDER-BRIDGE_R0603-0R]
SB60  (no value)  [SOLDER-BRIDGE_R0603-0R]
SB61  (no value)  [SOLDER-BRIDGE_R0603-0R]
SB62  (no value)  [SOLDER-BRIDGE_R0603-0R]
SB63  (no value)  [SOLDER-BRIDGE_R0603-0R]
SB64  (no value)  [SOLDER-BRIDGE_R0603-0R]
SB65  (no value)  [SOLDER-BRIDGE_R0603-0R]
SB66  (no value)  [SOLDER-BRIDGE_R0603-0R]
SB67  (no value)  [SOLDER-BRIDGE_R0603-0R]
SB68  (no value)  [SOLDER-BRIDGE_R0603-0R]
SB69  (no value)  [SOLDER-BRIDGE_R0603-0R]
SB70  (no value)  [SOLDER-BRIDGE_R0603-0R]
SB71  (no value)  [SOLDER-BRIDGE_R0603-0R]
SB72  (no value)  [SOLDER-BRIDGE_R0603-0R]
SB73  (no value)  [SOLDER-BRIDGE_R0603-0R]

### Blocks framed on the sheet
EXTENSION CONNECTORS, MCU INTERFACES: SB16-SB18

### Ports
ARD_D0_RX (in), ARD_D1_TX (out), NRST, PA[0..15] (bidir), PB[0..15] (bidir), PC[0..15] (bidir), PD[0..15] (bidir), PE[0..15] (bidir), PF[0..15] (bidir), PG[0..15] (bidir), PH3-BOOT0, PH[0..3] (bidir)

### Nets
1V8: SB16.1
3V3: CN8.7 CN11.16 R25.2 SB18.1
5V: CN8.9 CN11.18
5V_EXT: CN11.6
5V_USB_STLK: CN12.8
5V_VIN: R30.2
AGND: C65.1 CN10.3 CN12.32
GND: CN7.8 CN8.11 CN8.13 CN9.12 CN9.23 CN10.5 CN10.17 CN10.22 CN10.27 CN11.8 CN11.19 CN11.20 CN11.22 CN11.49 CN11.60 CN12.9 CN12.20 CN12.39 CN12.54 CN12.63 CN13.1(COMMON) CN13.2(NO) CN14.1(COMMON) CN14.2(NO) Q3.2(E) R45.1
IOREF: CN8.3 CN11.12 SB16.2 SB17.2 SB18.2
VBAT: CN11.33
VDD: CN11.5 SB17.1
VDDA: CN10.1
VIN: CN8.15 CN11.24
VREFP: C65.2 SB20.2
ARD_D0_RX: CN10.16 ; port ARD_D0_RX
ARD_D1_TX: CN10.14 ; port ARD_D1_TX
NRST: CN8.5 CN11.14 ; port NRST
PA0: CN11.28 SB60.1
PA1: CN10.11 CN11.30
PA2: CN12.35 SB56.1 SB57.1
PA3: CN9.1 CN12.37
PA4: CN11.32 SB35.1 SB38.1
PA5: CN7.10 CN12.11 SB23.1
PA6: CN7.12 CN12.13
PA7: CN7.14 CN12.15
PA8: CN10.31 CN12.23
PA9: CN12.21
PA10: CN12.33
PA11: CN12.14
PA12: CN12.12
PA13: CN11.13
PA14: CN11.15
PA15: CN11.17
PB0: SB63.1 SB64.1 SB65.2
PB1: CN10.7 CN12.24
PB2: CN9.13 CN12.22
PB3: CN7.15 CN12.31
PB4: CN12.27 SB36.1 SB43.1
PB5: CN12.29 SB37.1
PB6: CN9.15 CN12.17
PB7: CN11.21
PB8: CN7.2 CN12.3
PB9: CN7.4 CN12.5
PB10: CN12.25 SB61.1 SB62.2
PB11: CN10.34 CN12.18
PB13: CN7.5 CN12.30
PB14: CN12.28
PB15: CN12.26
PC0: CN9.11 CN11.38
PC1: CN9.9 CN11.36
PC2: CN11.35 SB53.1
PC3: CN9.5 CN11.37
PC6: CN7.1 CN12.4
PC7: CN12.19 SB21.1
PC8: CN8.2 SB19.2
PC9: CN8.4 SB22.1
PC10: CN8.6 CN11.1
PC11: CN8.8 CN11.2
PC12: CN8.10 CN11.3
PC13: CN11.23
PC14: CN11.25
PC15: CN11.27
PD0: CN9.25 CN11.57
PD1: CN9.27 CN11.55
PD2: CN8.12 CN11.4
PD3: CN9.10 CN11.40
PD4: CN9.8 CN11.39
PD5: CN9.6 CN11.41
PD6: CN9.4 CN11.43
PD7: CN9.2 CN11.45
PD8: CN12.10
PD9: CN11.69
PD10: CN12.65
PD11: CN7.3 CN12.45
PD12: CN7.7 CN12.43
PD13: CN12.41
PD14: CN7.16 CN12.46
PD15: CN7.18 CN12.48
PE0: CN10.33 CN12.64
PE1: CN11.61
PE2: CN9.14 CN11.46
PE3: CN9.22 CN11.47
PE4: CN9.16 CN11.48
PE5: CN9.18 CN11.50
PE6: CN9.20 CN11.62
PE7: CN10.20 CN12.44
PE8: CN10.18 CN12.40
PE9: CN10.4 CN12.52
PE10: CN10.24 CN12.47
PE11: CN10.6 CN12.56
PE12: CN12.49 SB68.1 SB69.2
PE13: CN10.10 CN12.55
PE14: CN12.51 SB70.1 SB71.2
PE15: CN12.53 SB66.1 SB67.2
PF0: CN9.21 CN11.53
PF1: CN9.19 CN11.51
PF2: CN9.17 CN11.52
PF3: CN8.14 CN12.58
PF4: CN12.38
PF5: CN8.16 CN12.36
PF6: CN11.9
PF7: CN9.26 CN11.11
PF8: CN9.24 CN11.54
PF9: CN9.28 CN11.56
PF10: CN12.42
PF11: CN12.62
PF12: CN7.20 CN12.59
PF13: CN10.2 CN12.57
PF14: CN10.8 CN12.50
PF15: CN10.12 CN12.60
PG0: CN9.29 CN11.59
PG1: CN9.30 CN11.58
PG2: CN11.42
PG3: CN11.44
PG4: CN12.69
PG5: CN12.68
PG6: CN12.70
PG7: SB73.1
PG8: SB72.2
PG9: CN11.63
PG10: CN11.66
PG12: CN11.65
PG13: CN11.68
PG14: CN12.61
PG15: CN11.64
PH0: CN11.29
PH1: CN11.31
PH3-BOOT0: CN11.7 ; port PH3-BOOT0
VREFP_ARD: CN7.6 CN12.7 SB20.1
NetCN7_9: CN7.9 SB35.2
NetCN7_11: CN7.11 SB36.2
NetCN7_13: CN7.13 SB37.2
NetCN7_17: CN7.17 SB38.2
NetCN7_19: CN7.19 SB43.2
NetCN8_1: CN8.1 R30.1
NetCN9_3: CN9.3 SB57.2
NetCN9_7: CN9.7 SB64.2
NetCN10_9: CN10.9 SB53.2
NetCN10_13: CN10.13 SB56.2
NetCN10_15: CN10.15 SB61.2
NetCN10_19: CN10.19 SB66.2
NetCN10_21: CN10.21 SB63.2
NetCN10_23: CN10.23 SB68.2
NetCN10_25: CN10.25 SB70.2
NetCN10_26: CN10.26 SB69.1
NetCN10_28: CN10.28 SB71.1
NetCN10_29: CN10.29 SB60.2
NetCN10_30: CN10.30 SB67.1
NetCN10_32: CN10.32 SB62.1
NetCN11_34: CN11.34 SB65.1
NetCN12_1: CN12.1 SB22.2
NetCN12_2: CN12.2 SB19.1
NetCN12_66: CN12.66 SB72.1
NetCN12_67: CN12.67 SB73.2
NetLD1_1: LD1.1 R25.1
NetLD1_2: LD1.2 Q3.3(C)
NetQ3_1: Q3.1(B) R45.2 R49.2
NetR49_1: R49.1 SB21.2 SB23.2

Not connected (* = marked no-connect by the designer): CN11 10* 26* 67* 70*; CN12 6* 16* 34*

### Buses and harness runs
bus PA[0..15] = port PA[0..15]
bus PB[0..15] = port PB[0..15]
bus PC[0..15] = port PC[0..15]
bus PD[0..15] = port PD[0..15]
bus PE[0..15] = port PE[0..15]
bus PF[0..15] = port PF[0..15]
bus PG[0..15] = port PG[0..15]
bus PH[0..3] = port PH[0..3]

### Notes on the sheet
- MORPHO CONNECTOR LEFT SIDE
- ZIO CONNECTOR ARDUINO UNO V3 COMPATIBLE
- MORPHO CONNECTOR RIGHT SIDE
- Arduino Uno compatible
- (near CN8) NC
- (near CN8) IOREF
- (near CN8) NRST
- (near CN8) SDMMC
- D43
- D44
- D45
- SDMMC_D0
- SDMMC_D1
- SDMMC_D2
- SAI_C_SD
- SAI_C_SCK
- SAI_C_MCLK
- D16
- D17
- D18
- (near CN7) SAI_C
- (near CN7) VREFP
- (near CN7) D14
- (near CN7) D15
- (near CN7) SCL
- (near CN7) SDA
- (near SB20) I2C_A_SCL
- I2C_A_SDA
- (near SB22) SB19/SB22 to avoid stub of SDMMC signals
- (near CN8) 3V3
- (near CN8) 5V
- (near CN8) GND
- (near CN8) VIN
- (near CN8) IO
- D46
- D47
- D48
- D49
- D50
- SDMMC_CK
- SDMMC_CMD
- SDMMC_D3
- IO
- SAI_C_FS
- SAI_D_SD/SPI_B_MOSI
- SAI_D_SCK/SPI_B_SCK
- SAI_D_FS
- SAI_D_MCLK
- D19
- D20
- D21
- D22
- D23
- (near CN7) SPI_B
- (near CN7) SAI_D
- (near CN7) D10
- (near CN7) D11
- (near CN7) D12
- (near CN7) D13
- (near CN7) SCK
- (near CN7) GND
- (near CN7) MISO
- (near CN7) MOSI/PWM
- (near CN7) CS/PWM
- SPI_A_CS/TIM_B_PWM3
- SPI_A_MOSI/TIM_E_PWM1
- SPI_A_SCK
- SPI_A_MISO
- PA2 & PB0 shared with QSPI
- SPI_B_MISO
- SPI_B_NSS
- D24
- D25
- (near CN7) D8
- (near CN7) D9
- (near CN7) PWM
- TIMER_B_PWM2
- A0
- A1
- A2
- A3
- (near CN9) A0
- (near CN9) A1
- (near CN9) A2
- (near CN9) A3
- (near CN9) USART
- D51
- D52
- D53
- D54
- USART_B_TX
- USART_B_RX
- USART_B_SCLK
- USART_B_RTS
- PC2 shared between USB C and ZIO
- (near CN10) GND
- (near CN10) AVDD
- (near CN10) AGND
- (near CN10) D7
- (near CN10) D6
- (near CN10) D5
- (near CN10) PWM
- TIMER_A_PWM1
- TIMER_A_PWM2
- (near SB65) SB65 to avoid stub of ADC A3 signals
- COMP
- COMP1_INP
- D72
- A4
- A5
- (near CN9) A4
- (near CN9) A5
- (near CN9) SAI_A
- (near CN9) GND
- D55
- D56
- SAI_A_MCLK
- USART_B_CTS
- QSPI_CLK
- QSPI_CS
- ADC_A_IN
- ADC_B_IN
- ADC_C_IN
- A6
- A7
- A8
- D26
- D27
- (near CN10) ADC
- (near CN10) QSPI
- (near CN10) D2
- (near CN10) D4
- (near CN10) D3
- (near CN10) D1
- (near CN10) D0
- (near CN10) TX
- (near CN10) RX
- PG8
- PG7
- TIMER_A_PWM3
- USART_A_TX
- USART_A_RX
- I2C_B
- I2C_B_SCL
- I2C_B_SDA
- I2C_B_SMBA
- COMP2_INP
- D71
- D70
- D69
- D68
- (near CN9) SAI_B
- D57
- D58
- D59
- D60
- D61
- SAI_A_SD
- SAI_A_SCK
- SAI_A_FS
- SAI_B_SD
- SAI_B_SCK
- QSPI_BK1_IO1
- QSPI_BK1_IO3
- D28
- D29
- (near CN10) TIMER
- D41
- D42
- TIMER_A_PWM1N
- TIMER_A_ETR
- CAN
- CAN_TX
- CAN_RX
- D67
- D66
- D65
- (near CN9) IO
- D62
- D63
- D64
- SAI_B_FS
- SAI_B_MCLK
- TIMER_D_PWM1
- TIMER_C_PWM1
- QSPI_BK1_IO0
- QSPI_BK1_IO2
- D30
- D31
- D32
- D33
- D36
- D37
- D38
- D39
- D40
- TIMER_A_PWM2N
- TIMER_A_PWM3N
- TIMER_C_PWM2
- TIMER_A_BKIN1
- TIMER_A_BKIN2
- TIMER_B_ETR
- D34
- PA2 & PB0 shared with Arduino_ADC
- TIMER
- D35
- TIMER_C_PWM3
- PE12, PE14, PE15 shared between TIMER for MOTOR-CONTROL and QSPI
- (near CN13) GND
- (near CN14) GND
- ARD_D13_LED
- D13

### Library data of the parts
C65 = MCD-00006: as C83 on sheet STM32_microcontroller_IOs
CN7 = MCD-01039: Socket, 10x2, 2.54mm, VR, TH, Height 8.51mm/10mm, Low insertion force.; Part_Type: Connector; Manufacturer_Part_Number: SSW-110-23-x-D; Manufacturer: SAMTEC; Provided_By: Subcon; Initial_Board_Reference: MB1361; Remark: Socket dedicated to Arduino+ZIO connector on NUCLEO144
CN8 = MCD-01037: Socket, 8x2, 2.54mm, VR, TH, Height 8.51mm/10mm, Low insertion force.; Part_Type: Connector; Manufacturer_Part_Number: SSW-108-23-x-D; Manufacturer: SAMTEC; Provided_By: Subcon; Initial_Board_Reference: MB1361; Remark: Socket dedicated to Arduino+ZIO connector on NUCLEO144
CN9 = MCD-01040: Socket, 15x2, 2.54mm, VR, TH, Height 8.51mm/10mm, Low insertion force.; Part_Type: Connector; Manufacturer_Part_Number: SSW-115-23-x-D; Manufacturer: SAMTEC; Provided_By: Subcon; Initial_Board_Reference: MB1361; Remark: Socket dedicated to Arduino+ZIO connector on NUCLEO144
CN10 = MCD-01041: Socket, 17x2, 2.54mm, VR, TH, Height 8.51mm/10mm, Low insertion force; Part_Type: Connector; Manufacturer_Part_Number: SSW-117-23-x-D; Manufacturer: SAMTEC; Provided_By: Subcon; Initial_Board_Reference: MB1361; Remark: Socket dedicated to Arduino+ZIO connector on NUCLEO144
CN11 CN12 = MCD-01210: Header, 35x2, 2,54mm, VR, TH, Height 5.84mm/2.54mm; Part_Type: Connector; Manufacturer_Part_Number: TSW-135-07-G-D; Manufacturer: SAMTEC; Part_Preference: Recommended
CN13 CN14 = MCD-00214: Header, 2x1, 2,54mm, VR, TH, Height 5.84mm/10.16mm; Manufacturer_Part_Number: TSW-102-09-x-S; Manufacturer: SAMTEC; Part_Type: Connector; Value: Header 2x1 16mm; Provided_By: Subcon; Initial_Board_Reference: MB1319
HW25 HW26 = MCD-00043: as HW5 on sheet STM32_microcontroller_power
LD1 = MCD-02900: LED, Green, 2V, 20mA, 0603; Part_Type: Display; Part_Preference: Recommended; Manufacturer: EVERLIGHT; Manufacturer_Part_Number: 19-213SYGC/S530-E2/5T; Full_Alternate_Internal_Part_Number: MCD-00320; Partial_Alternate_Internal_Part_Number: MCD-00050; Component_Country_Of_Origin: China; ShowFields: YES; ID: 5016
Q3 = MCD-00073: as Q4 on sheet STM32_microcontroller_IOs
R25 = MCD-00225: Resistor,510R,0603,1%,1/10W; Manufacturer_Part_Number: RC0603FR-07510RL; Manufacturer: YAGEO; Provided_By: Subcon; Initial_Board_Reference: MB1319
R30 = MCD-00070: as R24 on sheet STM32_microcontroller_IOs
R45 = MCD-00223: as R38 on sheet STM32_microcontroller_IOs
R49 = MCD-00222: as R50 on sheet STM32_microcontroller_IOs
SB16-SB23 SB35-SB38 SB43 SB53 SB56 SB57 SB60-SB73 = MCD-00071: as SB4 on sheet STM32_microcontroller_IOs

## Sheet USB_Type_C.SchDoc: USB_Type_C
size A4; Date: Not used; ApprovedBy: Not used; CheckedBy: Not used; Author: Not used; CompanyName: STMicroelectronics; DrawnBy: Not used; Engineer: Not used; Organization: Not used; Address1: Not used; Address2: Not used; Address3: Not used; Address4: Not used; DocumentNumber: 6; Revision: Not used; SheetNumber: 6; SheetTotal: 8
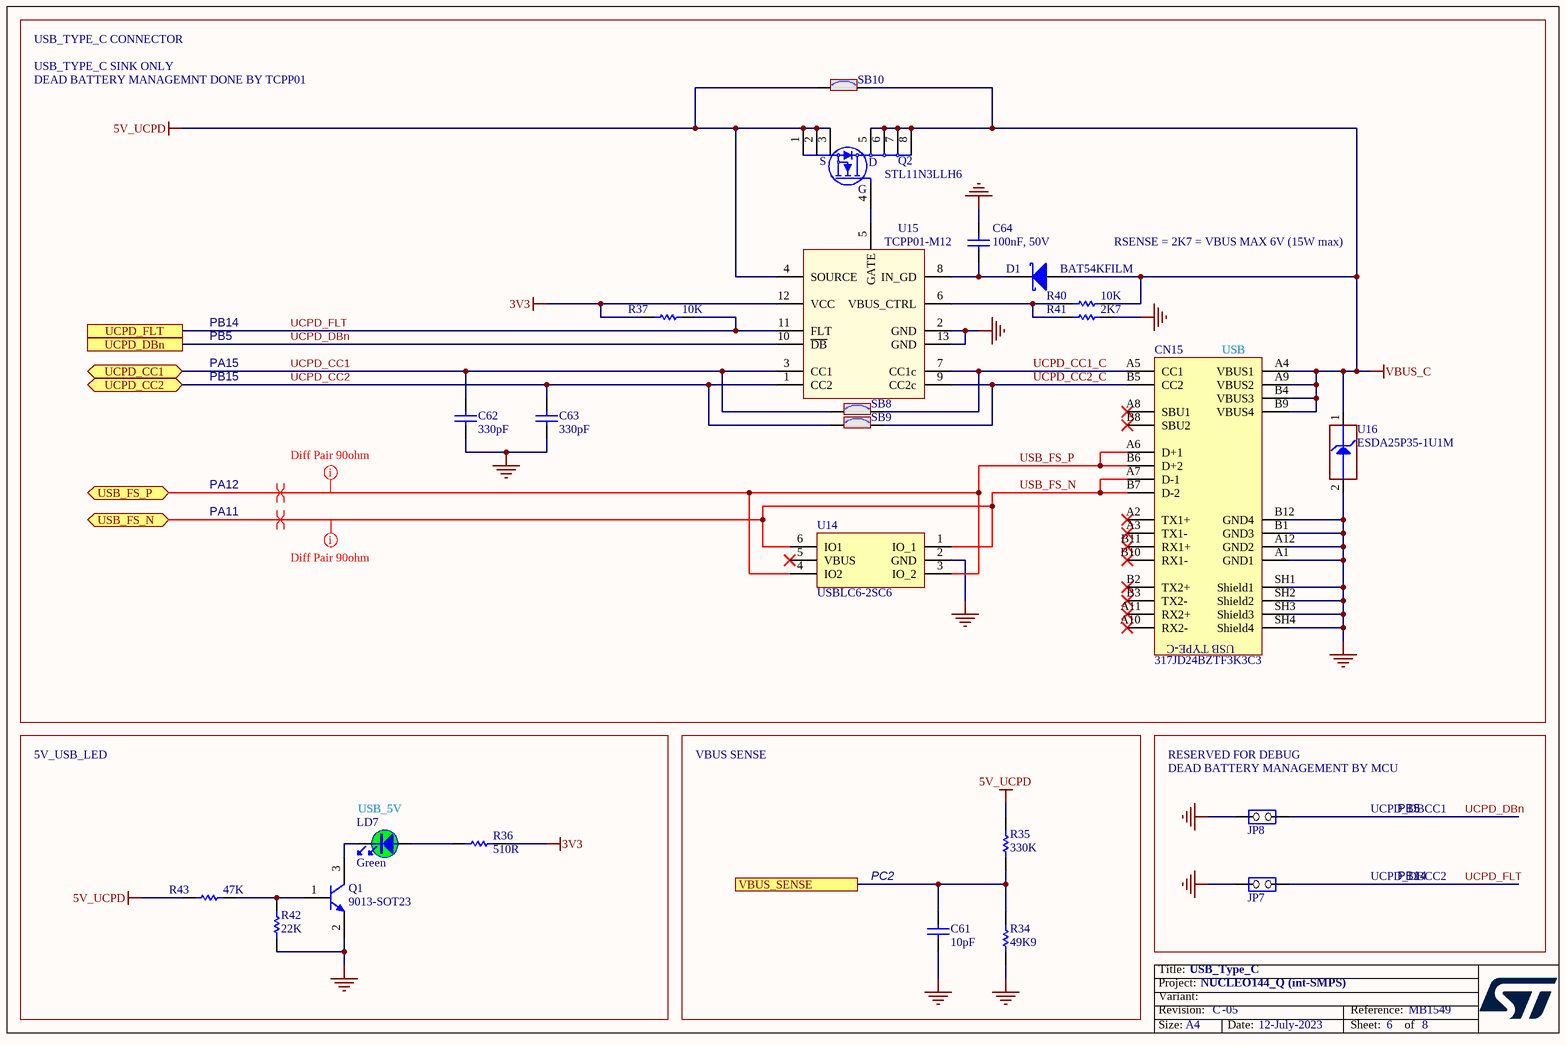
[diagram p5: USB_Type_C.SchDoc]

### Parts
C61  value 10pF  [C0603]
C62  value 330pF  [C0402]  (hidden comment: Capacitor)
C63  value 330pF  [C0402]  (hidden comment: Capacitor)
C64  value 100nF, 50V  [C0603]  (hidden comment: Capacitor)
CN15  value 317JD24BZTF3K3C3  [CON_USB-TYPEC_COXOC_317JD24BZTF3K3C3]  (hidden comment: USB_TYPE_C_Receptacle_317JD24BZTF3K3C3)
D1  value BAT54KFILM  [DIO_SOD523_1A_2K]  (hidden comment: SCHOTTKY_1A_2K)
JP7  Jumper_Header 2x1  [CON_SAMTEC_TSW-102-07-G-S]  (value not drawn)
JP8  Jumper_Header 2x1  [CON_SAMTEC_TSW-102-07-G-S]  (value not drawn)
LD7  value Green  [LED_0603_GREEN]  (hidden comment: LED_green)
Q1  value 9013-SOT23  [NPN_SOT23]
Q2  STL11N3LLH6  [MOS_POWERFLAT_3P3X3P3_P065]
R34  value 49K9  [R0603]
R35  value 330K  [R0603]
R36  value 510R  [R0603]
R37  value 10K  [R0402]  (hidden comment: Resistor)
R40  value 10K  [R0402]  (hidden comment: Resistor)
R41  value 2K7  [R0402]  (hidden comment: Resistor)
R42  value 22K  [R0603]
R43  value 47K  [R0603]
SB8  (no value)  [SOLDER-BRIDGE_R0603-0R]
SB9  (no value)  [SOLDER-BRIDGE_R0603-0R]
SB10  (no value)  [SOLDER-BRIDGE_R0603-0R]
U14  USBLC6-2SC6  [ESD_SOT23-6L]
U15  TCPP01-M12  [ICC_QFN12L-EPAD_3X3_P050]
U16  value ESDA25P35-1U1M  [ESD_QFN1610_2N_1K_2A]  (hidden comment: ESD-TRANSIL)

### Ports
UCPD_CC1 (bidir), UCPD_CC2 (bidir), UCPD_DBn, UCPD_FLT, USB_FS_N (bidir), USB_FS_P (bidir), VBUS_SENSE

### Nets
3V3: R36.1 R37.2 U15.12(VCC)
5V_UCPD: Q2.1(S) Q2.2(S) Q2.3(S) R35.2 R43.1 SB10.1 U15.4(SOURCE)
GND: C61.1 C62.1 C63.1 C64.1 CN15.A1(GND1) CN15.A12(GND2) CN15.B1(GND3) CN15.B12(GND4) CN15.SH1(Shield1) CN15.SH2(Shield2) CN15.SH3(Shield3) CN15.SH4(Shield4) JP7.2(NO) JP8.2(NO) Q1.2(E) R34.1 R41.1 R42.1 U14.2(GND) U15.2(GND) U15.13(GND) U16.2(GND)
VBUS_C: CN15.A4(VBUS1) CN15.A9(VBUS2) CN15.B4(VBUS3) CN15.B9(VBUS4) D1.1(A) Q2.5(D) Q2.6(D) Q2.7(D) Q2.8(D) R40.1 SB10.2 U16.1(IO1)
UCPD_CC1: C62.2 SB8.1 U15.3(CC1) ; port UCPD_CC1
UCPD_CC1_C: CN15.A5(CC1) SB8.2 U15.7(CC1c)
UCPD_CC2: C63.2 SB9.1 U15.1(CC2) ; port UCPD_CC2  [project net PB15]
UCPD_CC2_C: CN15.B5(CC2) SB9.2 U15.9(CC2c)
UCPD_DBn: JP8.1(COMMON) U15.10(~{DB}) ; port UCPD_DBn
UCPD_FLT: JP7.1(COMMON) R37.1 U15.11(FLT) ; port UCPD_FLT
USB_FS_N: CN15.A7(D-1) CN15.B7(D-2) U14.1(IO_1) U14.6(IO1) ; port USB_FS_N
USB_FS_P: CN15.A6(D+1) CN15.B6(D+2) U14.3(IO_2) U14.4(IO2) ; port USB_FS_P
VBUS_SENSE: C61.2 R34.2 R35.1 ; port VBUS_SENSE
NetC64_2: C64.2 D1.2(K) U15.8(IN_GD)
NetLD7_1: LD7.1 R36.2
NetLD7_2: LD7.2 Q1.3(C)
NetQ1_1: Q1.1(B) R42.2 R43.2
NetQ2_4: Q2.4(G) U15.5(GATE)
NetR40_2: R40.2 R41.2 U15.6(VBUS_CTRL)

Not connected (* = marked no-connect by the designer): CN15 A2(TX1+)* A3(TX1-)* A8(SBU1)* A10(RX2-)* A11(RX2+)* B2(TX2+)* B3(TX2-)* B8(SBU2)* B10(RX1-)* B11(RX1+)*; U14 5(VBUS)*

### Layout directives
mark named Diff Pair 90ohm: USB_FS_N, USB_FS_P
differential pair: USB_FS_N, USB_FS_P

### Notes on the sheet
- USB_TYPE_C CONNECTOR
- USB_TYPE_C SINK ONLY
- DEAD BATTERY MANAGEMNT DONE BY TCPP01
- RSENSE = 2K7 = VBUS MAX 6V (15W max)
- PA15
- PB15
- PB5
- PB14
- (near CN15) USB
- PA12
- PA11
- 5V_USB_LED
- VBUS SENSE
- RESERVED FOR DEBUG
- (near JP8) DEAD BATTERY MANAGEMENT BY MCU
- (near LD7) USB_5V
- (near JP8) UCPD_DBCC1
- PC2
- UCPD_DBCC2

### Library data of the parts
C61 = MCD-00637: Capacitor, MLCC, 10pF, 50V, NPO, 5%, 0603, T=0,8mm; Manufacturer_Part_Number: CC0603JRNPO9BN100; Manufacturer: YAGEO; Provided_By: subcon; Initial_Board_Reference: MB1319
C62 C63 = MCD-01579: Capacitor, MLCC, 330pF, 50V, NPO, +/-5%, 0402, T=0,5mm; Part_Preference: Recommended; Manufacturer: YAGEO; Manufacturer_Part_Number: CC0402JRNPO9BN331
C64 = MCD-01099: Capacitor,100nF,50V,X7R,10%,0603; Manufacturer_Part_Number: CC0603KRX7R9BB104; Manufacturer: YAGEO; Provided_By: SUBCO
CN15 = MCD-01108: USB tyce C certified receptacle for 1.6mm pcb height; Part_Type: Connector; Manufacturer: CHANT SINCERE (COXOC); Provided_By: SUBCO
D1 = MCD-01677: Small signal Schottky diodes; Part_Type: Diode; Manufacturer: STMICROELECTRONICS; ECCN_US: EAR99; ECCN_EU: NEC; Provided_By: SUBCO
JP7 JP8 = MCD-00045: Header, 2x1, 2,54mm, VR, TH, Height 5.84mm/2.54mm; Part_Type: Connector; Manufacturer_Part_Number: TSW-102-07-x-S; Manufacturer: SAMTEC; Alternate_Manufacturer_Part_Number: 313102S111116;313102S111116; Alternate_Manufacturer: JIUBABA; LIANYI; Value: Shunt not fitted; Provided_By: SUBCO
LD7 = MCD-02900: as LD1 on sheet ARDUINO_extension_connectors
Q1 = MCD-00073: as Q4 on sheet STM32_microcontroller_IOs
Q2 = MCD-01810: N-channel 30 V, 6 mΩ typ, 11 A STripFET™ H6, Power MOSFET in a PowerFLAT™ 3.3x3.3 package; Part_Type: IC; Manufacturer: STMICROELECTRONICS; ECCN_US: EAR99; ECCN_EU: NEC; Provided_By: SUBCO with ST control
R34 = MCD-01171: Resistor,49K9,0603,1%; Manufacturer_Part_Number: RC0603FR-0749K9L; Manufacturer: YAGEO; Provided_By: Subcon; Initial_Board_Reference: MB1397
R35 = MCD-00458: Resistor,330K,0603,1%,1/10W; Manufacturer_Part_Number: RC0603FR-07330KL; Manufacturer: YAGEO; Provided_By: Subcon
R36 = MCD-00225: as R25 on sheet ARDUINO_extension_connectors
R37 R40 = MCD-00053: as R31 on sheet STM32_microcontroller_IOs
R41 = MCD-00055: Resistor,2K7,0402,1%,1/16W; Manufacturer_Part_Number: RC0402FR-072K7L; Manufacturer: YAGEO; Provided_By: SUBCO; ECCN_US: EAR99; ECCN_EU: NEC
R42 = MCD-00430: Resistor,22K,0603,1%,1/10W; Manufacturer_Part_Number: RC0603FR-0722KL; Manufacturer: YAGEO; Provided_By: Subcon
R43 = MCD-00222: as R50 on sheet STM32_microcontroller_IOs
SB8-SB10 = MCD-00071: as SB4 on sheet STM32_microcontroller_IOs
U14 = MCD-00163: Very low capacitance ESD protection; Part_Type: IC; Manufacturer: STMICROELECTRONICS; BMS_Part_Number: 9151075; ECCN_US: EAR99; ECCN_EU: NEC; Provided_By: SUBCO with ST control
U15 = MCD-01809: USB Type-C Port Protection for USB Power Delivery, PPS compliant; Part_Type: IC; Manufacturer: STMICROELECTRONICS; ECCN_US: EAR99; ECCN_EU: NEC; Provided_By: SUBCO with ST control
U16 = MCD-01207: High power Transient voltage suppressor:25V/35A EOS and ESD transients protection.; Part_Type: Diode; Manufacturer: STMICROELECTRONICS; BMS_Part_Number: 9179045; ECCN_US: EAR99; ECCN_EU: NEC; Provided_By: SUBCO with ST control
